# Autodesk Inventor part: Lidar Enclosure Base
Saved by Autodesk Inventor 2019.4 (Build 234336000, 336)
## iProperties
Created: 2020-05
Part Number: Lidar Enclosure Base
Material: Generic
Document SubType Name: Modeling
Designer: Administrator
Density: 1 g/cm^3
Appearance: Default
Title: Lidar Enclosure Base
Author: Administrator
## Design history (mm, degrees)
feature "Body1"
body "Solid1"
